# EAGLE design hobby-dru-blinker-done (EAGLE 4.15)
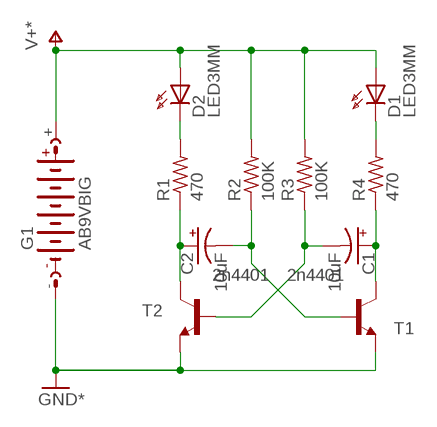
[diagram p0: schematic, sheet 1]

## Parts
C1  10uF  CPOL-USTAP5-50  [TAP5-50]
C2  10uF  CPOL-USTAP5-50  [TAP5-50]
D1  LED3MM  [LED3MM]
D2  LED3MM  [LED3MM]
G1  AB9VBIG  [9VCLIP]
R1  470  R-US_0207/10  [0207/10]
R2  100K  R-US_0207/10  [0207/10]
R3  100K  R-US_0207/10  [0207/10]
R4  470  R-US_0207/10  [0207/10]
T1  2n4401  NPN-GENERICEBC  [TO92-]
T2  2n4401  NPN-GENERICEBC  [TO92-]

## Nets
GND [power]: G1.- T1.3(E) T2.3(E) ; supply symbol labelled GND*
N$2: C2.+ R1.1 T2.1(C)
N$3: D2.K(C) R1.2
N$5: C2.- R2.1 T1.2(B)
N$9: D1.K(C) R4.2
N$10: C1.+ R4.1 T1.1(C)
N$12: C1.- R3.1 T2.2(B)
V+ [power]: D1.A D2.A G1.+ R2.2 R3.2 ; supply symbol labelled V+*

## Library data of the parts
C1 C2 = rcl:CPOL-US: POLARIZED CAPACITOR, American symbol
D1 D2 = led:LED3MM: LED
G1 = battery:AB9V: 9-V BATTERY CLIP
R1-R4 = rcl:R-US_: RESISTOR, American symbol
T1 T2 = transistor-npn:NPN-GENERIC: Generic NPN transistor in a variety of packages

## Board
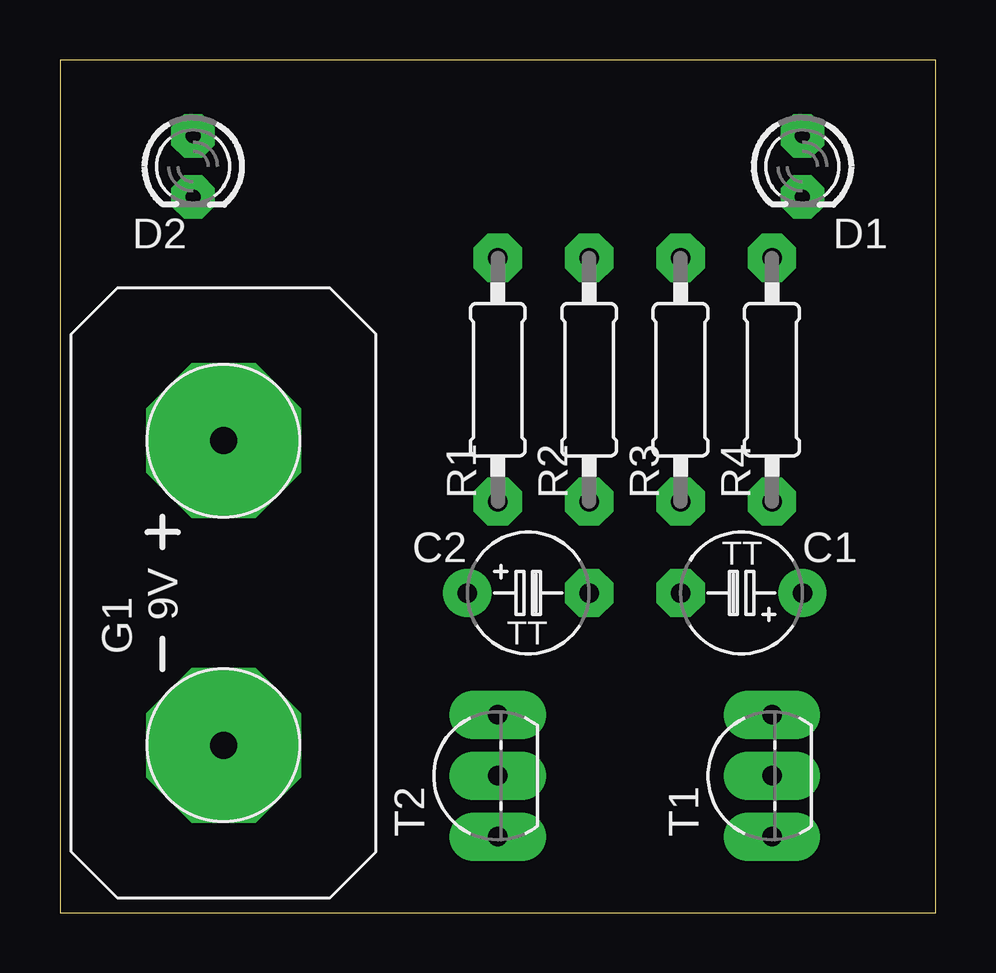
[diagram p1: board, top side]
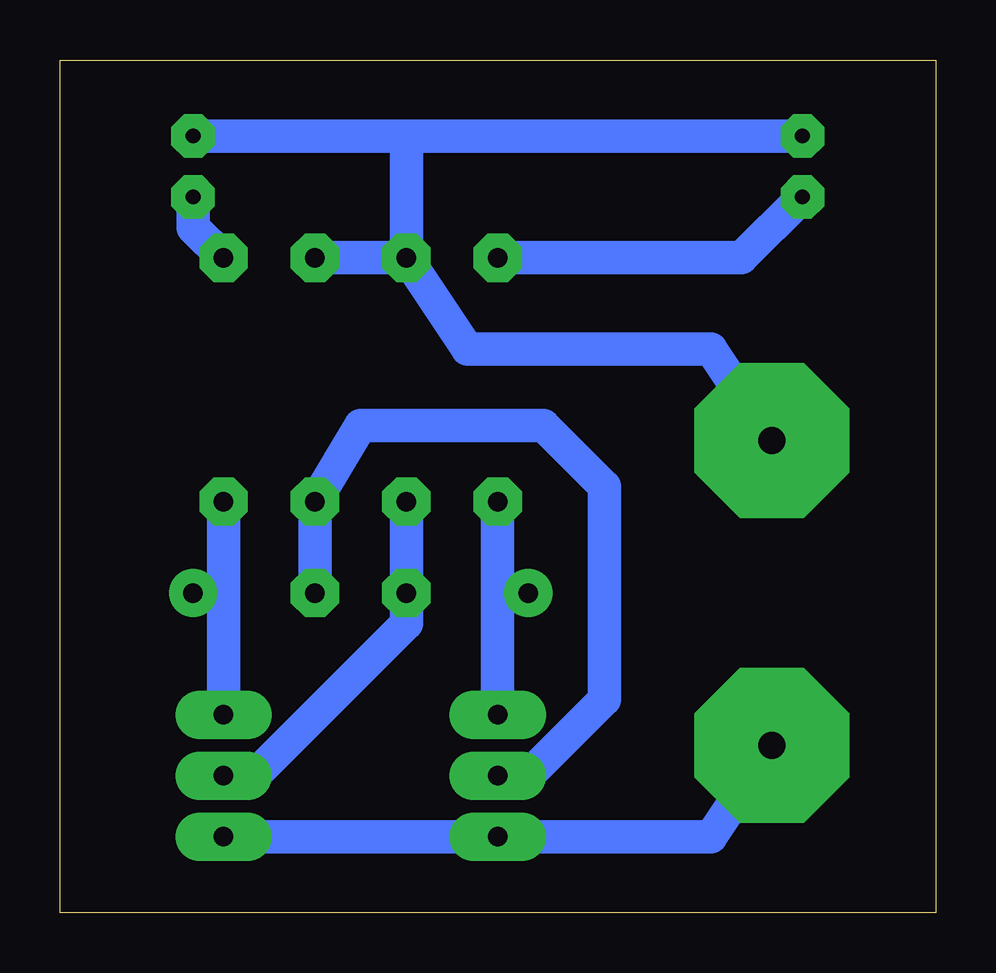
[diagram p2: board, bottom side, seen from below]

Size 36.5 x 35.55 mm. Coordinates in mm from the lower left corner, seen from the top.
Outline: 0,0 36.5,0 36.5,35.55 0,35.55 0,0
Copper layers (1*16): Top 0.035mm / dielectric 1.5mm / Bottom 0.035mm
Design rules "hobby": minimum track width 0.8mm, minimum drill 0.8mm, track to track 0.8mm, track to pad 0.8mm, pad to pad 0.45mm, via to via 0.8mm, smd to smd 8mil, copper to edge 10mil, drill to drill 8mil, minimum pad ring 0.6mm, minimum via ring 0.55mm, stop-mask expansion 0mil, vias tented up to drill 0mil, thermal gap 10mil

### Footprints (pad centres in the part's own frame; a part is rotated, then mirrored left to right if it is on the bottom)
TAP5-50 = drill 0.813 round: + -2.54,0 | drill 0.813 octagon: - 2.54,0
LED3MM = drill 0.61 octagon: A -1.27,0; K 1.27,0
9VCLIP = drill 1.118 pad 6.452 octagon: + 0,6.35; - 0,-6.35
0207/10 = drill 0.813 octagon: 1 -5.08,0; 2 5.08,0
TO92- = drill 0.813 long: 1 2.54,-1.27; 2 0,-1.27; 3 -2.54,-1.27

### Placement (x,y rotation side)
C1  28.41,13.33 180 top
C2  19.52,13.33 0 top
D1  30.95,31.11 270 top
D2  5.55,31.11 270 top
G1  6.82,13.33 0 top
R1  18.25,22.22 90 top
R2  22.06,22.22 90 top
R3  25.87,22.22 90 top
R4  29.68,22.22 90 top
T1  28.41,5.71 90 top
T2  16.98,5.71 90 top

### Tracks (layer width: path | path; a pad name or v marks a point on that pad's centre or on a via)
GND
  Bottom 1.4: T1.3 T2.3 9.36,3.17 G1.-
N$2
  Bottom 1.4: 18.25,13.33 R1.1 | T2.1 18.25,13.33 | 18.25,13.33 C2.+
N$3
  Bottom 1.4: D2.K 8.09,27.3 R1.2
N$5
  Bottom 1.4: T1.2 28.41,5.71 22.06,12.06 C2.- R2.1
N$9
  Bottom 1.4: D1.K 30.95,28.57 R4.2
N$10
  Bottom 1.4: 29.68,13.33 R4.1 | T1.1 29.68,13.33 | 29.68,13.33 C1.+
N$12
  Bottom 1.4: T2.2 16.98,5.71 13.8,8.88 13.8,17.77 16.34,20.32 23.96,20.32 R3.1 C1.-
V+
  Bottom 1.4: R2.2 R3.2 | 22.06,32.38 D1.A | 22.06,32.38 D2.A | R2.2 22.06,32.38 | R2.2 19.52,23.49 9.36,23.49 G1.+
